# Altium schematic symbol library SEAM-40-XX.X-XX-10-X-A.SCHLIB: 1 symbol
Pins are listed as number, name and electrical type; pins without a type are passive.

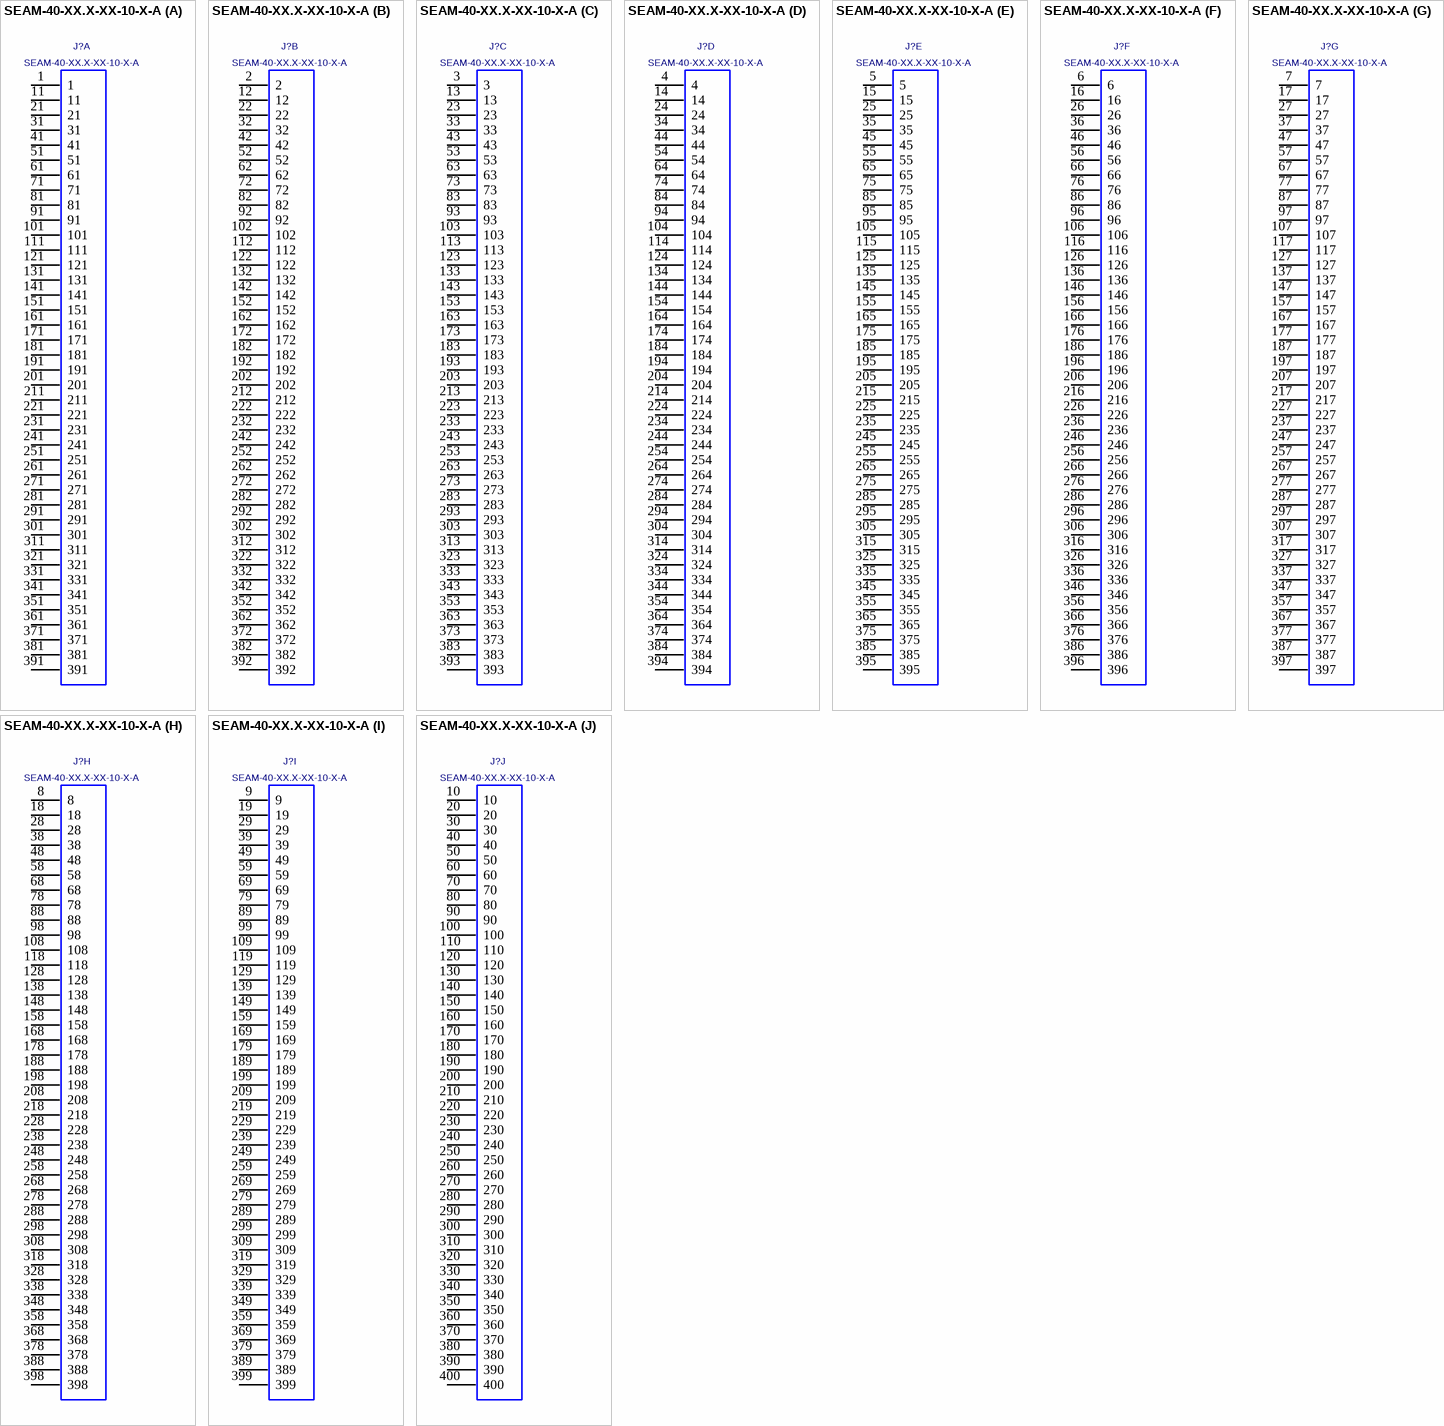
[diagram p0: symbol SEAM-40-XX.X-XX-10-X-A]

## SEAM-40-XX.X-XX-10-X-A
designator J?
Terminal Array Assembly, Surface Mount, 0.050" Pitch, 400 Pins; MANUFACTURER: SAMTEC
footprint SEAM-40-XX.X-XX-10-X-A
part A pins: 1, 11, 21, 31, 41, 51, 61, 71, 81, 91, 101, 111, 121, 131, 141, 151, 161, 171, 181, 191, 201, 211, 221, 231, 241, 251, 261, 271, 281, 291, 301, 311, 321, 331, 341, 351, 361, 371, 381, 391
part B pins: 2, 12, 22, 32, 42, 52, 62, 72, 82, 92, 102, 112, 122, 132, 142, 152, 162, 172, 182, 192, 202, 212, 222, 232, 242, 252, 262, 272, 282, 292, 302, 312, 322, 332, 342, 352, 362, 372, 382, 392
part C pins: 3, 13, 23, 33, 43, 53, 63, 73, 83, 93, 103, 113, 123, 133, 143, 153, 163, 173, 183, 193, 203, 213, 223, 233, 243, 253, 263, 273, 283, 293, 303, 313, 323, 333, 343, 353, 363, 373, 383, 393
part D pins: 4, 14, 24, 34, 44, 54, 64, 74, 84, 94, 104, 114, 124, 134, 144, 154, 164, 174, 184, 194, 204, 214, 224, 234, 244, 254, 264, 274, 284, 294, 304, 314, 324, 334, 344, 354, 364, 374, 384, 394
part E pins: 5, 15, 25, 35, 45, 55, 65, 75, 85, 95, 105, 115, 125, 135, 145, 155, 165, 175, 185, 195, 205, 215, 225, 235, 245, 255, 265, 275, 285, 295, 305, 315, 325, 335, 345, 355, 365, 375, 385, 395
part F pins: 6, 16, 26, 36, 46, 56, 66, 76, 86, 96, 106, 116, 126, 136, 146, 156, 166, 176, 186, 196, 206, 216, 226, 236, 246, 256, 266, 276, 286, 296, 306, 316, 326, 336, 346, 356, 366, 376, 386, 396
part G pins: 7, 17, 27, 37, 47, 57, 67, 77, 87, 97, 107, 117, 127, 137, 147, 157, 167, 177, 187, 197, 207, 217, 227, 237, 247, 257, 267, 277, 287, 297, 307, 317, 327, 337, 347, 357, 367, 377, 387, 397
part H pins: 8, 18, 28, 38, 48, 58, 68, 78, 88, 98, 108, 118, 128, 138, 148, 158, 168, 178, 188, 198, 208, 218, 228, 238, 248, 258, 268, 278, 288, 298, 308, 318, 328, 338, 348, 358, 368, 378, 388, 398
part I pins: 9, 19, 29, 39, 49, 59, 69, 79, 89, 99, 109, 119, 129, 139, 149, 159, 169, 179, 189, 199, 209, 219, 229, 239, 249, 259, 269, 279, 289, 299, 309, 319, 329, 339, 349, 359, 369, 379, 389, 399
part J pins: 10, 20, 30, 40, 50, 60, 70, 80, 90, 100, 110, 120, 130, 140, 150, 160, 170, 180, 190, 200, 210, 220, 230, 240, 250, 260, 270, 280, 290, 300, 310, 320, 330, 340, 350, 360, 370, 380, 390, 400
